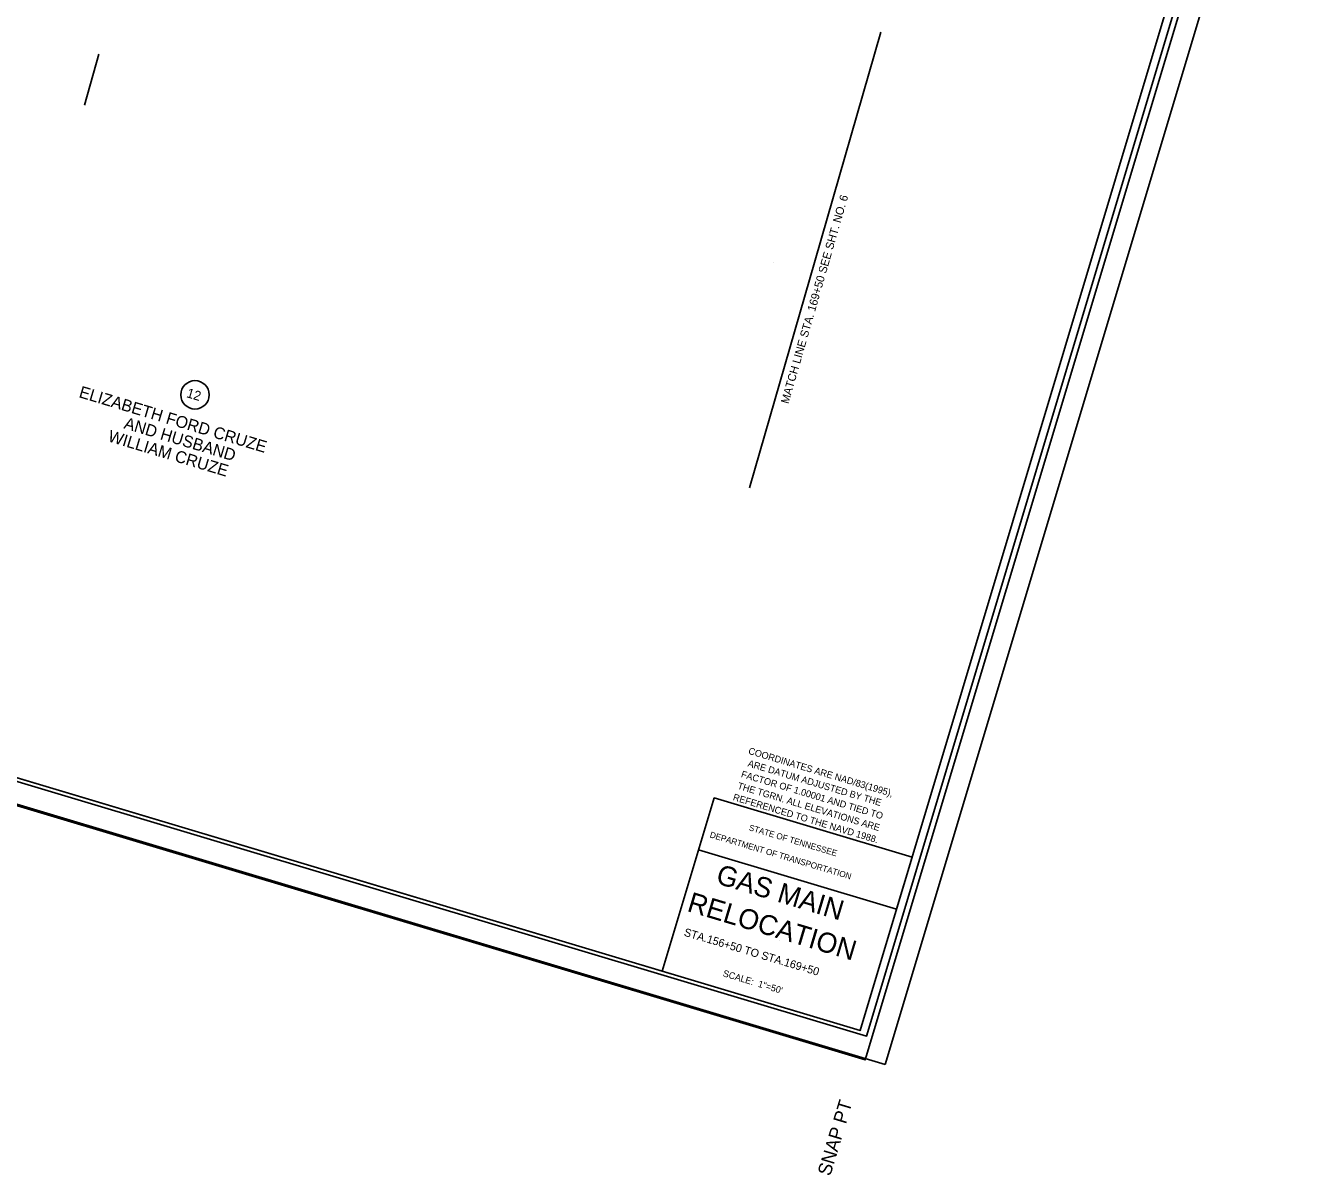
# Model space of a CAD drawing. Extents: x 2627582 to 2629622, y 568931 to 570612.
# Drawn here: x 2628672 to 2629619, y 568931 to 569779 of the extents above; entities that cross this region are included whole.
import ezdxf

# ---------------------------------------------------------------- set-up
doc = ezdxf.new("R2010")
doc.units = 0
for name, color, linetype in [('DESIGN - CENTERLINE - Proposed Text', 7, 'Continuous'), ('DESIGN - SCRATCH - User 1', 7, 'Continuous'), ('DESIGN - SHEET - Corner Text', 7, 'Continuous'), ('DESIGN - SHEET - Light Grid', 7, 'Continuous'), ('DESIGN - SHEET - Linework', 7, 'Continuous'), ('DESIGN - SHEET - Plot Shape', 7, 'Continuous'), ('SURVEY - PROJECT INFORMATION and NOTES', 7, 'Continuous'), ('SURVEY - PROPERTY - Owners', 7, 'Continuous'), ('SURVEY - PROPERTY - Tract Numbers', 7, 'Continuous')]:
    doc.layers.add(name, color=color, linetype=linetype)

msp = doc.modelspace()

# ---------------------------------------------------------------- linework, layer by layer
at = {"layer": 'DESIGN - CENTERLINE - Proposed Text'}
msp.add_lwpolyline([(2629206.17, 569438.02), (2629254.54, 569606.2), (2629302.91, 569774.39)], dxfattribs=at)
at = {"layer": 'DESIGN - SCRATCH - User 1'}
for p, q in [((2629223.72, 569604.66), (2629223.72, 569604.66)), ((2629228.13, 569104.12), (2629228.13, 569104.12))]:
    msp.add_line(p, q, dxfattribs=at)
at = {"layer": 'DESIGN - SHEET - Light Grid'}
msp.add_lwpolyline([(2627697.64, 569511.43), (2629292.52, 569033.35), (2629595.46, 570043.92), (2628000.57, 570522.01)], close=True, dxfattribs=at)
at = {"layer": 'DESIGN - SHEET - Linework'}
for p in [(2629618.55, 570053.91), (2627582.11, 569529.15)]:
    msp.add_line(p, (2629306.31, 569012.3), dxfattribs=at)
for points in [[(2628081.32, 570495.19), (2627779.83, 569489.41), (2629287.73, 569037.39), (2629589.23, 570043.18), (2628081.32, 570495.19)], [(2629141.66, 569081.18), (2629180.03, 569209.2), (2629326.11, 569165.42), (2629314.62, 569127.1), (2629168.55, 569170.89)]]:
    msp.add_lwpolyline(points, dxfattribs=at)
at = {"layer": 'DESIGN - SHEET - Plot Shape'}
for points in [[(2627975.91, 570547.35), (2629604.32, 570059.22), (2629291.51, 569015.7), (2627663.1, 569503.83)], [(2627999.85, 570519.61), (2629589.23, 570043.18), (2629287.73, 569037.39), (2627698.36, 569513.83)]]:
    msp.add_lwpolyline(points, close=True, dxfattribs=at)
at = {"layer": 'SURVEY - PROJECT INFORMATION and NOTES'}
msp.add_line((2628725.96, 569758.22), (2628715.26, 569720.68), dxfattribs=at)
at = {"layer": 'SURVEY - PROPERTY - Tract Numbers'}
msp.add_circle((2628796.81, 569506.74), 10.5, dxfattribs=at)

# ---------------------------------------------------------------- texts
at = {"layer": 'DESIGN - CENTERLINE - Proposed Text'}
msp.add_text('MATCH LINE STA. 169+50 SEE SHT. NO. 6', height=6, rotation=73.95539, dxfattribs=at).set_placement((2629234.84, 569499.71))
at = {"layer": 'DESIGN - SHEET - Corner Text'}
for s, height, rotation, p in [('COORDINATES ARE NAD/83(1995),', 5.0001, 343.31329, (2629204.81, 569241.81)), ('ARE DATUM ADJUSTED BY THE', 5.0001, 343.31329, (2629204.38, 569232.55)), ('FACTOR OF 1.00001 AND TIED TO', 5.0001, 343.31329, (2629199.47, 569224.62)), ('THE TGRN. ALL ELEVATIONS ARE', 5.0001, 343.31329, (2629196.82, 569216.02)), ('REFERENCED TO THE NAVD 1988.', 5.0001, 343.31329, (2629193.49, 569207.62)), ('STATE OF TENNESSEE', 4.5, 343.31329, (2629205.25, 569185.36)), ('DEPARTMENT OF TRANSPORTATION', 4.5, 343.31329, (2629176.43, 569180.11)), ('GAS MAIN', 14.764, 343.31329, (2629180.52, 569146.33)), ('RELOCATION', 14.764, 343.31329, (2629159.32, 569125.79)), ('STA.156+50 TO STA.169+50', 5.9055, 343.31329, (2629157.26, 569107.55)), ('SCALE:  1"=50\'', 4.9215, 343.31329, (2629186.02, 569077.6)), ('SNAP PT  ', 10, 73.31329, (2629265.67, 568929.49))]:
    msp.add_text(s, height=height, rotation=rotation, dxfattribs=at).set_placement(p)
at = {"layer": 'SURVEY - PROPERTY - Owners'}
for s, p in [('ELIZABETH FORD CRUZE', (2628710.57, 569505.09)), ('AND HUSBAND', (2628743.75, 569482.09)), ('WILLIAM CRUZE', (2628732.02, 569472.56))]:
    msp.add_text(s, height=8.75, rotation=343.31329, dxfattribs=at).set_placement(p)
at = {"layer": 'SURVEY - PROPERTY - Tract Numbers'}
msp.add_text('12', height=7, rotation=343.31329, dxfattribs=at).set_placement((2628790.06, 569505.11))

doc.saveas('drawing.dxf')
